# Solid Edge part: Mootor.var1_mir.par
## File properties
Author: jaanm
Template: Ansi Inch Part.par
Last saved by: jaanm
Revision: 4
Application: Solid Edge
Accuracy: 0,990
Username: jaanm
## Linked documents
Mootor.var1.par
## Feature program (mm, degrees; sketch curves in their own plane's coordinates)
part copy "CopiedPart_1"
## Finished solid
Body 1: solid body, 246 faces, 556 edges, 298 vertices, 2 separate solids.
  Faces by surface: plane 220, cylinder 21, cone 3, spline 2
  Edges by curve: line 416, ellipse 80, circle 33, intersection 26, spline 1
Bounding box of the edges (mm; curved faces can reach further): 450.120 x 650.000 x 369.541, from (-267.6032, -400, -184.7705) to (182.5166, 250, 184.7705).
Cylindrical faces by radius (mm): R5 x16, R33.9209 x1, R100 x1, R110 x1, R115 x1, R125 x1
Conical faces (half-angle, radius in mm at the cone's reference point): 45 deg R115 x1, 45 deg R120 x1, 45 deg R125 x1
Planar faces by outward normal: +x 3, +y 6, +z 3, -x 4, -y 4, -z 3, oblique 197
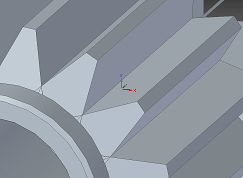
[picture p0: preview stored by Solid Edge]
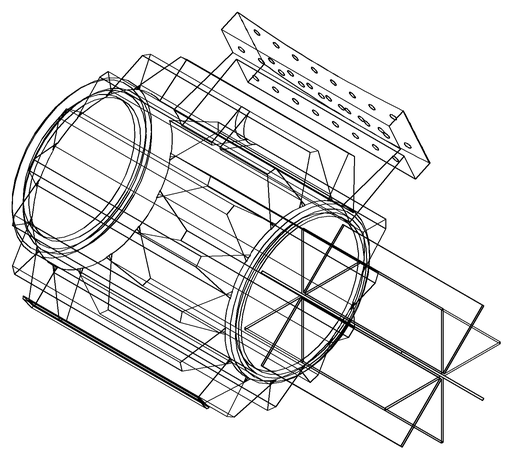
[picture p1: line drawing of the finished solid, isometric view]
